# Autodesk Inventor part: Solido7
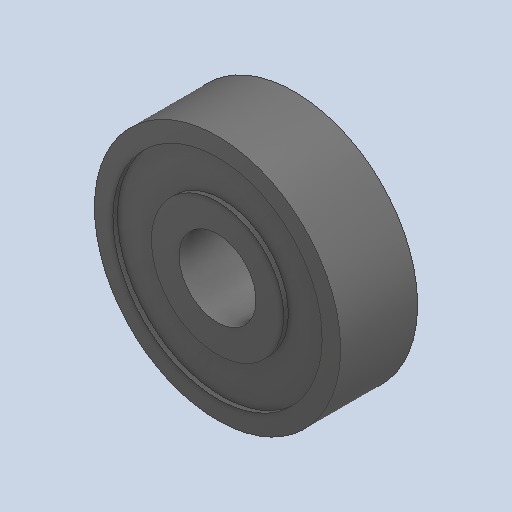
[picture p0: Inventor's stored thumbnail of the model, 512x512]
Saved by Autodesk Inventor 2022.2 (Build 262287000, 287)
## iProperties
Created: 2024-10
Part Number: Solido7
Material: Generico
Document SubType Name: Modeling
Designer: 18907419
Density: 1 g/cm^3
Appearance: Default
Author: 18907419
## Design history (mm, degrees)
feature "Solido7"
node "Solido1"
